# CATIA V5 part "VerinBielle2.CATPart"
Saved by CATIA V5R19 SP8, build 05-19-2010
Part number: VérinBielle
Bounding box of the stored display mesh (mm): x -65 to 160, y -40 to 40, z -40 to 40
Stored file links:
  C:\Users\ThinkMotion\Desktop\EU_thinkMotion\iao\IAO_MMS_Groupe3\yschmidt\Train1434_yschmidt\Train1434_yschmidt\VerinBielle2.CATPart
  C:\Users\ThinkMotion\Desktop\EU_thinkMotion\iao\IAO_MMS_Groupe3\yschmidt\Train1434_yschmidt\Train1434_yschmidt\AssemblageTrainOptimise.CATProduct
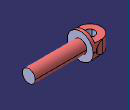
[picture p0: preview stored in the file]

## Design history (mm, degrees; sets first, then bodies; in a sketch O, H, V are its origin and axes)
Set1
  Plane1: linked copy from another document
  Line1: linked copy from another document
Body1 (main body)
  Sketch1 on yz-plane, origin (0, 0, 0), H (0, 1, 0), V (0, 0, 1)
    circle A1 centre (0, 0) radius 20
    radius A1 = 20
  Pad1: profile Sketch1, direction (1, 0, 0), up to Plane1
  Sketch2 on start face of Pad1, origin (0, 0, 0), H (0, -1, 0), V (0, 0, 1)
    circle A1 centre (0, 0) radius 40
    radius A1 = 40
  Pad2: profile Sketch2, direction (-1, 0, 0), length 10
  SolidCombine1: FirstComponentProfile Sketch4, FirstComponentDirection Sketch4, SecondComponentProfile Sketch5, SecondComponentDirection Sketch5
  Sketch3 on face of SolidCombine1 from Sketch4.L2, origin (-63.3728, 12.2345, -20), H (1, 0, 0), V (0, -1, 0)
    point P1 (33.3728, 12.2345)
    reference projected point E1 (33.3728, 12.2345) from Line1
    coincidence: P1 E1
  Hole1: placed by Sketch3, at (-30, 0, -20) direction (0, 0, 1), diameter 30, through (limit type 6)
  Sketch4 on end face of Pad2, origin (-10, 0, 0), H (0, -1, 0), V (0, 0, 1)
    arc A1 centre (0, 0) radius 40 from (34.641, -20) to (34.641, 20) ccw
    point P1 (0, 0)
    reference projected circle E1 centre (0, 0) radius 40 from edge [face of Pad2 from Sketch2.A1 | end face of Pad2]
    line L1 (-34.641, 20) -> (34.641, 20)
    point P2 (-34.641, 20)
    line L2 (34.641, -20) -> (-34.641, -20)
    arc A2 centre (0, 0) radius 40 from (-34.641, 20) to (-34.641, -20) ccw
    reference projected line E2 (29.986, 0) -> (44.2515, 0) from Sketch5.A3
    reference projected line E3 (-29.986, 0) -> (29.986, 0) from Sketch5.A1
    reference projected line E4 (-29.986, 0) -> (29.986, 0) from Sketch5.A1
    distance L1 E2 = 20
    distance E3 E4 = 0 (reference)
    distance L2 H = 20
    coincidence: P1 H, A1 E1, P2 A1, A1 A2
    horizontal: L1 H, L2 H
  Sketch5 on xy-plane, origin (0, 0, 0), H (1, 0, 0), V (0, 1, 0)
    arc A1 centre (-30, 0) radius 35 from (-34.9286, 34.6512) to (-34.9286, -34.6512) ccw
    line L1 (-12.6267, 39.2789) -> (-10, 40)
    point P2 (-28.3552, 34.9613)
    point P3 (-10, 40)
    axis line L2 (-132.7013, 0) -> (62.1574, 0)
    point P4 (-132.7013, 0)
    reference projected line E1 (-10, -45) -> (-10, 45) from edge [face of Pad2 from Sketch2.A1 | end face of Pad2]
    point P6 (-10, -40)
    line L3 (-12.6267, -39.2789) -> (-10, -40)
    arc A2 centre (-60.2758, 212.8576) radius 180 from (-34.9286, 34.6512) to (-12.6267, 39.2789) ccw
    point P7 (-34.9286, 34.6512)
    point P8 (-12.6267, 39.2789)
    point P10 (-12.6267, -39.2789)
    point P11 (-34.9286, -34.6512)
    arc A3 centre (-60.2758, -212.8576) radius 180 from (-34.9286, -34.6512) to (-12.6267, -39.2789) cw
    line L4 (-10, 40) -> (-10, -40)
    reference projected point E2 (-30, 0) from Line1
    radius A2 = 180
    distance P3 L2 = 40
    distance A1 L4 = 55
    coincidence: P2 A1, P4 H, P3 E1, L1 P2
    horizontal: L2 H
    symmetry: P3 P6 L2, L1 L3 L2, P8 P10 L2, P7 P11 L2, A2 A3 L2
    tangency: A2 A1, A2 L1
    vertical: L4 V
    concentricity: A1 E2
